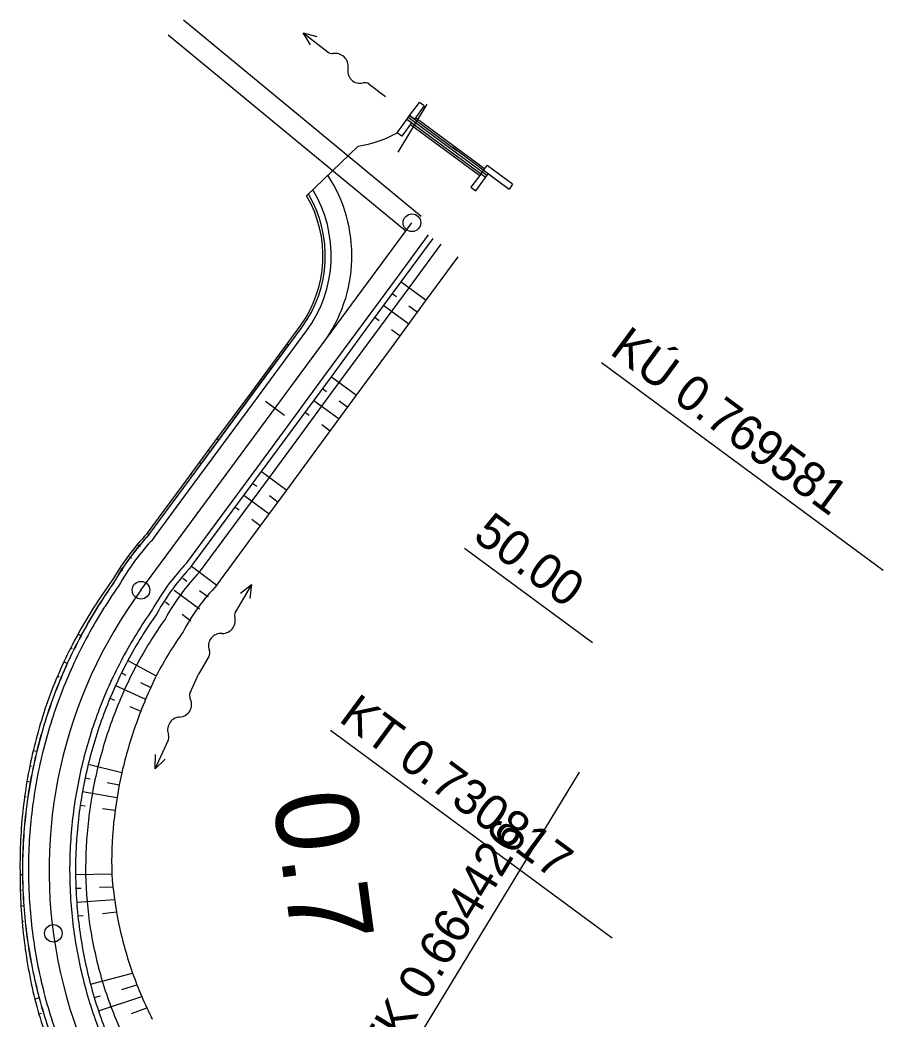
# Model space of a CAD drawing. Extents: x -481645 to -478728, y -1113199 to -1110710.
# Drawn here: x -479819.6 to -479746.4, y -1112732.9 to -1112648.1 of the extents above; entities that cross this region are included whole.
import ezdxf

# ---------------------------------------------------------------- set-up
doc = ezdxf.new("R2010")
doc.units = 0
for name, color, linetype in [('CP14_HECTOMETRY', 7, 'Continuous'), ('CP14_HLBODY', 7, 'Continuous'), ('CP14_HRANA_TELESO', 7, 'Continuous'), ('CP14_OSA', 7, 'Continuous'), ('CP14_PRIKOP', 7, 'Continuous'), ('CP14_STANICENI', 7, 'Continuous'), ('CP14_VOZOVKA', 7, 'Continuous'), ('CP14_ZPEVKRAJ', 7, 'Continuous'), ('CP1_HATCH_SLOPE_L', 7, 'Continuous'), ('CP1_HATCH_SLOPE_R', 7, 'Continuous'), ('CP1_HLBODY', 7, 'Continuous'), ('CP1_HRANA_TELESO', 7, 'Continuous'), ('CP1_OSA', 7, 'Continuous'), ('CP1_STANICENI', 7, 'Continuous'), ('CP1_VOZOVKA', 7, 'Continuous'), ('CP1_ZPEVKRAJ', 7, 'Continuous')]:
    doc.layers.add(name, color=color, linetype=linetype)

# ---------------------------------------------------------------- blocks, each defined once
blk = doc.blocks.new('A$C70B')
at = {"layer": 'CP14_HLBODY'}
for p, q in [((0.869, 0.002), (-0.869, -0.002)), ((6.861, 0.426), (7.971, -0.002)), ((7.971, -0.002), (5.275, -0.002)), ((7.971, -0.002), (6.862, -0.478))]:
    blk.add_line(p, q, dxfattribs=at)
for centre, radius, start, end in [((0.872, 0.584), 0.582, 269.69241, 322.79009), ((2.168, -0.416), 1.055, 24.40393, 142.08362), ((4.08, 0.589), 1.109, 210.88731, 317.37071), ((5.319, -0.636), 0.636, 85.97658, 131.72478)]:
    blk.add_arc(centre, radius, start, end, dxfattribs=at)

msp = doc.modelspace()

# ---------------------------------------------------------------- linework, layer by layer
at = {"layer": 'CP14_HRANA_TELESO'}
for p, q in [((-479796.825, -1112675.729), (-479796.948, -1112675.638)), ((-479797.632, -1112676.686), (-479797.69, -1112676.644)), ((-479797.567, -1112676.735), (-479797.571, -1112676.732)), ((-479798.309, -1112677.741), (-479798.432, -1112677.65)), ((-479799.116, -1112678.698), (-479799.174, -1112678.656)), ((-479799.05, -1112678.747), (-479799.054, -1112678.744)), ((-479802.76, -1112683.778), (-479802.915, -1112683.663)), ((-479803.584, -1112684.724), (-479803.657, -1112684.669)), ((-479803.502, -1112684.784), (-479803.506, -1112684.781)), ((-479804.244, -1112685.79), (-479804.399, -1112685.675)), ((-479805.068, -1112686.736), (-479805.141, -1112686.681)), ((-479804.986, -1112686.796), (-479804.99, -1112686.793)), ((-479808.695, -1112691.826), (-479808.846, -1112691.715)), ((-479809.52, -1112692.771), (-479809.594, -1112692.716)), ((-479809.437, -1112692.832), (-479809.441, -1112692.829)), ((-479810.179, -1112693.838), (-479810.342, -1112693.717)), ((-479811.01, -1112694.778), (-479811.09, -1112694.719)), ((-479810.921, -1112694.844), (-479810.925, -1112694.841)), ((-479814.453, -1112700.385), (-479814.714, -1112700.245)), ((-479815.199, -1112701.488), (-479815.333, -1112701.422)), ((-479815.056, -1112701.559), (-479815.06, -1112701.557)), ((-479815.622, -1112702.752), (-479815.914, -1112702.619)), ((-479816.308, -1112703.896), (-479816.457, -1112703.833)), ((-479816.15, -1112703.962), (-479816.155, -1112703.96)), ((-479818.213, -1112710.226), (-479818.526, -1112710.149)), ((-479818.663, -1112711.48), (-479818.809, -1112711.449)), ((-479818.507, -1112711.513), (-479818.512, -1112711.512)), ((-479818.76, -1112712.808), (-479819.052, -1112712.756)), ((-479819.118, -1112714.09), (-479819.253, -1112714.07)), ((-479818.973, -1112714.111), (-479818.978, -1112714.11)), ((-479819.422, -1112720.691), (-479819.633, -1112720.693)), ((-479819.508, -1112722.016), (-479819.617, -1112722.02)), ((-479819.388, -1112722.011), (-479819.393, -1112722.011)), ((-479819.313, -1112723.329), (-479819.56, -1112723.347)), ((-479819.334, -1112724.658), (-479819.461, -1112724.672)), ((-479819.197, -1112724.644), (-479819.202, -1112724.644)), ((-479818.004, -1112731.13), (-479818.386, -1112731.232)), ((-479817.843, -1112732.46), (-479818.032, -1112732.517)), ((-479817.645, -1112732.401), (-479817.649, -1112732.402))]:
    msp.add_line(p, q, dxfattribs=at)
at = {"layer": 'CP14_OSA'}
msp.add_circle((-479816.81, -1112725.652), 0.75, dxfattribs=at)
at = {"layer": 'CP14_PRIKOP'}
for p, q in [((-479787.268, -1112670.352), (-479785.157, -1112671.909)), ((-479788.01, -1112671.358), (-479787.673, -1112671.606)), ((-479788.752, -1112672.364), (-479786.633, -1112673.926)), ((-479786.616, -1112672.386), (-479785.895, -1112672.918)), ((-479789.494, -1112673.37), (-479789.156, -1112673.618)), ((-479788.095, -1112674.401), (-479787.371, -1112674.935)), ((-479793.203, -1112678.4), (-479791.07, -1112679.973)), ((-479793.945, -1112679.406), (-479793.608, -1112679.654)), ((-479794.687, -1112680.412), (-479792.55, -1112681.988)), ((-479792.54, -1112680.442), (-479791.81, -1112680.981)), ((-479795.429, -1112681.418), (-479795.092, -1112681.666)), ((-479794.023, -1112682.455), (-479793.291, -1112682.995)), ((-479799.138, -1112686.448), (-479796.992, -1112688.031)), ((-479799.88, -1112687.454), (-479799.543, -1112687.703)), ((-479800.622, -1112688.46), (-479798.473, -1112690.045)), ((-479798.469, -1112688.495), (-479797.732, -1112689.038)), ((-479801.364, -1112689.466), (-479801.027, -1112689.715)), ((-479799.951, -1112690.508), (-479799.213, -1112691.052)), ((-479805.074, -1112694.497), (-479802.914, -1112696.089)), ((-479805.815, -1112695.503), (-479805.478, -1112695.752)), ((-479806.557, -1112696.509), (-479804.387, -1112698.109)), ((-479804.396, -1112696.55), (-479803.651, -1112697.099)), ((-479807.299, -1112697.515), (-479806.962, -1112697.764)), ((-479805.875, -1112698.566), (-479805.124, -1112699.119)), ((-479810.482, -1112702.502), (-479808.07, -1112703.789)), ((-479811.021, -1112703.552), (-479810.646, -1112703.736)), ((-479811.527, -1112704.617), (-479808.978, -1112705.779)), ((-479809.406, -1112704.349), (-479808.54, -1112704.777)), ((-479811.999, -1112705.698), (-479811.61, -1112705.861)), ((-479810.303, -1112706.408), (-479809.384, -1112706.792)), ((-479813.842, -1112711.295), (-479810.986, -1112711.994)), ((-479814.105, -1112712.445), (-479813.69, -1112712.533)), ((-479812.243, -1112712.84), (-479811.211, -1112713.058)), ((-479814.331, -1112713.603), (-479811.404, -1112714.128)), ((-479814.521, -1112714.767), (-479814.101, -1112714.829)), ((-479812.622, -1112715.047), (-479811.563, -1112715.203)), ((-479814.922, -1112720.646), (-479811.846, -1112720.615)), ((-479814.892, -1112721.825), (-479814.458, -1112721.807)), ((-479812.885, -1112721.742), (-479811.747, -1112721.695)), ((-479814.825, -1112723.003), (-479811.614, -1112722.77)), ((-479814.721, -1112724.178), (-479814.274, -1112724.132)), ((-479812.637, -1112723.961), (-479811.447, -1112723.837)), ((-479813.655, -1112729.973), (-479810.083, -1112729.023)), ((-479811.007, -1112730.41), (-479809.71, -1112730.022)), ((-479813.334, -1112731.108), (-479812.819, -1112730.954)), ((-479812.978, -1112732.233), (-479809.306, -1112731.006)), ((-479810.185, -1112732.458), (-479808.873, -1112731.974))]:
    msp.add_line(p, q, dxfattribs=at)
at = {"layer": 'CP14_STANICENI'}
msp.add_line((-479795.305, -1112663.043), (-479790.933, -1112658.823), dxfattribs=at)
for centre, radius, start, end in [((-479792.206, -1112649.726), 9.185, 277.97005, 299.91517), ((-479803.963, -1112668.139), 10.75, 323.59269, 31.37909), ((-479803.993, -1112668.156), 10.081, 323.86732, 30.47383), ((-479803.963, -1112668.139), 10.25, 323.59269, 30.75296)]:
    msp.add_arc(centre, radius, start, end, dxfattribs=at)
at = {"layer": 'CP14_VOZOVKA'}
for p, q in [((-479805.765, -1112648.12), (-479785.577, -1112664.776)), ((-479807.065, -1112649.375), (-479786.877, -1112666.031)), ((-479787.52, -1112659.35), (-479785.056, -1112655.265))]:
    msp.add_line(p, q, dxfattribs=at)
msp.add_arc((-479803.963, -1112668.139), 12.5, 323.59269, 33.16788, dxfattribs=at)
at = {"layer": 'CP14_ZPEVKRAJ'}
for p, q in [((-479786.557, -1112656.24), (-479785.725, -1112655.113)), ((-479785.323, -1112655.41), (-479786.154, -1112656.537)), ((-479785.323, -1112655.41), (-479785.725, -1112655.113)), ((-479787.626, -1112657.688), (-479786.794, -1112656.561)), ((-479786.794, -1112656.561), (-479786.557, -1112656.24)), ((-479782.348, -1112659.845), (-479786.794, -1112656.561)), ((-479786.392, -1112656.858), (-479786.794, -1112656.561)), ((-479779.995, -1112661.333), (-479786.675, -1112656.4)), ((-479786.557, -1112656.239), (-479782.512, -1112659.226)), ((-479786.154, -1112656.537), (-479786.557, -1112656.24)), ((-479780.19, -1112660.754), (-479786.065, -1112656.416)), ((-479786.392, -1112656.858), (-479787.224, -1112657.985)), ((-479786.481, -1112656.979), (-479780.606, -1112661.318)), ((-479787.224, -1112657.985), (-479787.626, -1112657.688)), ((-479779.877, -1112661.172), (-479782.914, -1112658.929)), ((-479780.114, -1112661.494), (-479783.152, -1112659.251)), ((-479780.279, -1112660.875), (-479779.983, -1112660.472)), ((-479777.811, -1112662.067), (-479779.983, -1112660.472)), ((-479780.517, -1112661.197), (-479781.348, -1112662.323)), ((-479780.946, -1112662.62), (-479780.114, -1112661.494)), ((-479780.517, -1112661.197), (-479780.279, -1112660.875)), ((-479780.279, -1112660.875), (-479778.11, -1112662.468)), ((-479780.114, -1112661.494), (-479779.877, -1112661.172)), ((-479781.348, -1112662.323), (-479780.946, -1112662.62)), ((-479777.814, -1112662.065), (-479778.11, -1112662.468))]:
    msp.add_line(p, q, dxfattribs=at)
at = {"layer": 'CP1_HATCH_SLOPE_L'}
for p, q in [((-479797.177, -1112681.682), (-479798.786, -1112680.495)), ((-479781.885, -1112692.959), (-479771.02, -1112700.972))]:
    msp.add_line(p, q, dxfattribs=at)
at = {"layer": 'CP1_HATCH_SLOPE_R'}
for p, q in [((-479770.264, -1112677.2), (-479746.361, -1112694.828)), ((-479793.271, -1112708.398), (-479769.367, -1112726.025)), ((-479787.567, -1112737.356), (-479772.133, -1112711.981))]:
    msp.add_line(p, q, dxfattribs=at)
for centre in [(-479786.36, -1112665.33), (-479809.367, -1112696.527)]:
    msp.add_circle(centre, 0.75, dxfattribs=at)
at = {"layer": 'CP1_HLBODY'}
for p, q in [((-479787.67, -1112670.055), (-479784.952, -1112666.369)), ((-479790.638, -1112674.079), (-479787.67, -1112670.055)), ((-479793.605, -1112678.103), (-479790.638, -1112674.079)), ((-479796.573, -1112682.127), (-479793.605, -1112678.103)), ((-479802.358, -1112684.074), (-479799.39, -1112680.05)), ((-479799.541, -1112686.152), (-479796.573, -1112682.127)), ((-479805.325, -1112688.098), (-479802.358, -1112684.074)), ((-479802.508, -1112690.176), (-479799.541, -1112686.152)), ((-479808.293, -1112692.122), (-479805.325, -1112688.098)), ((-479805.476, -1112694.2), (-479802.508, -1112690.176))]:
    msp.add_line(p, q, dxfattribs=at)
for centre, radius, start, end in [((-479793.084, -1112706.422), 20.875, 136.76418, 150.61946), ((-479791.666, -1112707.43), 19.125, 136.22776, 151.14187), ((-479777.174, -1112720.268), 41.75, 144.76332, 151.92529), ((-479777.174, -1112720.268), 38.25, 144.76331, 151.92528), ((-479777.174, -1112720.268), 41.75, 151.92529, 159.08726), ((-479777.174, -1112720.268), 38.25, 151.92528, 159.08726), ((-479777.174, -1112720.268), 41.75, 159.08726, 166.24924), ((-479777.174, -1112720.268), 38.25, 159.08726, 166.24923), ((-479777.174, -1112720.268), 41.75, 166.24924, 173.41121), ((-479777.174, -1112720.268), 38.25, 166.24923, 173.4112), ((-479777.174, -1112720.268), 41.75, 173.41121, 180.57318), ((-479777.174, -1112720.268), 38.25, 173.4112, 180.57317), ((-479777.174, -1112720.268), 41.75, 180.57318, 187.73515), ((-479777.174, -1112720.268), 38.25, 180.57317, 187.73514), ((-479777.174, -1112720.268), 41.75, 187.73515, 194.89713), ((-479777.174, -1112720.268), 38.25, 187.73514, 194.89712), ((-479777.174, -1112720.268), 38.25, 194.89712, 202.05909), ((-479777.174, -1112720.268), 41.75, 194.89713, 202.0591)]:
    msp.add_arc(centre, radius, start, end, dxfattribs=at)
at = {"layer": 'CP1_HRANA_TELESO'}
for p, q in [((-479785.157, -1112671.909), (-479782.424, -1112668.234)), ((-479788.109, -1112675.944), (-479785.157, -1112671.909)), ((-479799.917, -1112679.662), (-479795.852, -1112674.1)), ((-479791.07, -1112679.973), (-479788.109, -1112675.944)), ((-479802.915, -1112683.663), (-479799.917, -1112679.662)), ((-479794.031, -1112684.002), (-479791.07, -1112679.973)), ((-479805.884, -1112687.687), (-479802.915, -1112683.663)), ((-479796.992, -1112688.031), (-479794.031, -1112684.002)), ((-479808.846, -1112691.715), (-479805.884, -1112687.687)), ((-479799.954, -1112692.06), (-479796.992, -1112688.031)), ((-479802.914, -1112696.089), (-479799.954, -1112692.06))]:
    msp.add_line(p, q, dxfattribs=at)
for centre, radius, start, end in [((-479793.441, -1112706.33), 21.234, 136.50563, 150.16536), ((-479777.505, -1112720.797), 42.508, 143.92415, 151.08689), ((-479790.322, -1112708.271), 17.52, 135.94864, 152.02132), ((-479777.336, -1112720.619), 42.571, 151.40625, 158.56852), ((-479777.072, -1112720.101), 35.029, 145.08335, 152.24543), ((-479776.743, -1112719.283), 34.949, 153.68312, 160.84848), ((-479777.12, -1112720.092), 42.583, 159.33516, 166.4972), ((-479777.005, -1112719.71), 34.845, 160.04478, 167.20775), ((-479777.104, -1112719.864), 42.546, 166.80102, 173.96332), ((-479777.085, -1112719.747), 34.776, 167.11831, 174.28111), ((-479777.152, -1112719.79), 42.49, 174.05545, 181.21788), ((-479777.15, -1112719.715), 34.708, 174.32379, 181.48668), ((-479777.136, -1112720.855), 42.497, 179.78211, 186.94476), ((-479777.416, -1112717.988), 34.53, 184.36389, 191.54165), ((-479777.797, -1112717.681), 34.22, 192.17183, 199.35546), ((-479777.009, -1112721.141), 42.589, 186.5414, 193.70493), ((-479778.169, -1112717.655), 33.879, 199.60558, 206.79196), ((-479777.083, -1112720.543), 42.663, 194.50961, 201.67174)]:
    msp.add_arc(centre, radius, start, end, dxfattribs=at)
at = {"layer": 'CP1_OSA'}
msp.add_line((-479809.367, -1112696.527), (-479786.36, -1112665.33), dxfattribs=at)
msp.add_arc((-479777.174, -1112720.268), 40, 143.59269, 238.69063, dxfattribs=at)
at = {"layer": 'CP1_STANICENI'}
for p, q in [((-479787.67, -1112670.055), (-479784.952, -1112666.369)), ((-479790.638, -1112674.079), (-479787.67, -1112670.055)), ((-479793.605, -1112678.103), (-479790.638, -1112674.079)), ((-479799.39, -1112680.05), (-479795.311, -1112674.52)), ((-479796.573, -1112682.127), (-479793.605, -1112678.103)), ((-479802.358, -1112684.074), (-479799.39, -1112680.05)), ((-479799.541, -1112686.152), (-479796.573, -1112682.127)), ((-479805.325, -1112688.098), (-479802.358, -1112684.074)), ((-479802.508, -1112690.176), (-479799.541, -1112686.152)), ((-479808.293, -1112692.122), (-479805.325, -1112688.098)), ((-479805.476, -1112694.2), (-479802.508, -1112690.176))]:
    msp.add_line(p, q, dxfattribs=at)
for centre, radius, start, end in [((-479793.084, -1112706.422), 20.875, 136.76418, 150.61946), ((-479791.666, -1112707.43), 19.125, 136.22776, 151.14187), ((-479777.174, -1112720.268), 41.75, 144.76332, 151.92529), ((-479777.174, -1112720.268), 38.25, 144.76331, 151.92528), ((-479777.174, -1112720.268), 41.75, 151.92529, 159.08726), ((-479777.174, -1112720.268), 38.25, 151.92528, 159.08726), ((-479777.174, -1112720.268), 41.75, 159.08726, 166.24924), ((-479777.174, -1112720.268), 38.25, 159.08726, 166.24923), ((-479777.174, -1112720.268), 41.75, 166.24924, 173.41121), ((-479777.174, -1112720.268), 38.25, 166.24923, 173.4112), ((-479777.174, -1112720.268), 41.75, 173.41121, 180.57318), ((-479777.174, -1112720.268), 38.25, 173.4112, 180.57317), ((-479777.174, -1112720.268), 41.75, 180.57318, 187.73515), ((-479777.174, -1112720.268), 38.25, 180.57317, 187.73514), ((-479777.174, -1112720.268), 41.75, 187.73515, 194.89713), ((-479777.174, -1112720.268), 38.25, 187.73514, 194.89712), ((-479777.174, -1112720.268), 38.25, 194.89712, 202.05909), ((-479777.174, -1112720.268), 41.75, 194.89713, 202.0591)]:
    msp.add_arc(centre, radius, start, end, dxfattribs=at)
at = {"layer": 'CP1_VOZOVKA'}
for p, q in [((-479787.268, -1112670.352), (-479784.55, -1112666.666)), ((-479790.235, -1112674.376), (-479787.268, -1112670.352)), ((-479799.792, -1112679.753), (-479795.714, -1112674.223)), ((-479793.203, -1112678.4), (-479790.235, -1112674.376)), ((-479796.171, -1112682.424), (-479793.203, -1112678.4)), ((-479802.76, -1112683.778), (-479799.792, -1112679.753)), ((-479799.138, -1112686.448), (-479796.171, -1112682.424)), ((-479805.728, -1112687.802), (-479802.76, -1112683.778)), ((-479802.106, -1112690.472), (-479799.138, -1112686.448)), ((-479808.695, -1112691.826), (-479805.728, -1112687.802)), ((-479805.073, -1112694.497), (-479802.106, -1112690.472))]:
    msp.add_line(p, q, dxfattribs=at)
for centre, radius, start, end in [((-479793.287, -1112706.278), 21.125, 136.83359, 150.55201), ((-479791.463, -1112707.574), 18.875, 136.14304, 151.22455), ((-479777.174, -1112720.268), 42.25, 144.76332, 151.92529), ((-479777.174, -1112720.268), 37.75, 144.76331, 151.92528), ((-479777.174, -1112720.268), 42.25, 151.92529, 159.08726), ((-479777.174, -1112720.268), 37.75, 151.92528, 159.08726), ((-479777.174, -1112720.268), 42.25, 159.08726, 166.24924), ((-479777.174, -1112720.268), 37.75, 159.08726, 166.24923), ((-479777.174, -1112720.268), 42.25, 166.24924, 173.41121), ((-479777.174, -1112720.268), 37.75, 166.24923, 173.4112), ((-479777.174, -1112720.268), 42.25, 173.41121, 180.57318), ((-479777.174, -1112720.268), 37.75, 173.4112, 180.57317), ((-479777.174, -1112720.268), 42.25, 180.57318, 187.73515), ((-479777.174, -1112720.268), 37.75, 180.57317, 187.73514), ((-479777.174, -1112720.268), 42.25, 187.73515, 194.89713), ((-479777.174, -1112720.268), 37.75, 187.73514, 194.89712), ((-479777.174, -1112720.268), 37.75, 194.89712, 202.05909), ((-479777.174, -1112720.268), 42.25, 194.89713, 202.0591)]:
    msp.add_arc(centre, radius, start, end, dxfattribs=at)
at = {"layer": 'CP1_ZPEVKRAJ'}
for p, q in [((-479786.594, -1112670.849), (-479783.875, -1112667.163)), ((-479789.561, -1112674.873), (-479786.594, -1112670.849)), ((-479792.529, -1112678.897), (-479789.561, -1112674.873)), ((-479799.8, -1112679.747), (-479796.833, -1112675.723)), ((-479795.497, -1112682.921), (-479792.529, -1112678.897)), ((-479802.768, -1112683.772), (-479799.8, -1112679.747)), ((-479798.464, -1112686.946), (-479795.497, -1112682.921)), ((-479805.736, -1112687.796), (-479802.768, -1112683.772)), ((-479801.432, -1112690.97), (-479798.464, -1112686.946)), ((-479808.703, -1112691.82), (-479805.736, -1112687.796)), ((-479804.399, -1112694.994), (-479801.432, -1112690.97))]:
    msp.add_line(p, q, dxfattribs=at)
for centre, radius, start, end in [((-479793.291, -1112706.275), 21.13, 136.83496, 150.55068), ((-479791.124, -1112707.815), 18.456, 135.99598, 151.36819), ((-479777.174, -1112720.268), 42.26, 144.76332, 151.92529), ((-479777.201, -1112720.312), 36.916, 144.68354, 151.84552), ((-479777.174, -1112720.268), 42.26, 151.92529, 159.08726), ((-479777.123, -1112720.156), 36.911, 152.11568, 159.27769), ((-479777.174, -1112720.268), 42.26, 159.08726, 166.24924), ((-479777.171, -1112720.259), 36.903, 159.10287, 166.26484), ((-479777.174, -1112720.268), 42.26, 166.24924, 173.41121), ((-479777.172, -1112720.259), 36.902, 166.26461, 173.42658), ((-479777.174, -1112720.268), 42.26, 173.41121, 180.57318), ((-479777.172, -1112720.218), 36.898, 173.48881, 180.65079), ((-479777.174, -1112720.268), 42.26, 180.57318, 187.73515), ((-479777.21, -1112719.81), 36.866, 181.28645, 188.44898), ((-479777.375, -1112719.329), 36.777, 189.2276, 196.39201), ((-479777.174, -1112720.268), 42.26, 187.73515, 194.89713), ((-479777.633, -1112718.977), 36.632, 197.03356, 204.20053), ((-479777.174, -1112720.268), 42.26, 194.89713, 202.0591)]:
    msp.add_arc(centre, radius, start, end, dxfattribs=at)

# ---------------------------------------------------------------- block references
at = {"layer": 'CP14_HECTOMETRY'}
for p, rotation in [((-479789.305, -1112654.098), 142.2083198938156), ((-479804.038, -1112702.9), 59.384220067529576), ((-479804.839, -1112704.44), -114.58073141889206)]:
    msp.add_blockref('A$C70B', p, dxfattribs=dict(at, rotation=rotation))

# ---------------------------------------------------------------- texts
at = {"layer": 'CP14_OSA'}
msp.add_text('0.7', height=7, rotation=277.68952, dxfattribs=at).set_placement((-479798.202, -1112714))
at = {"layer": 'CP1_HATCH_SLOPE_L'}
msp.add_text('50.00', height=2.999, rotation=323.5927, dxfattribs=at).set_placement((-479781.292, -1112692.154))
at = {"layer": 'CP1_HATCH_SLOPE_R'}
for s, height, rotation, p in [('KÚ 0.769581', 2.999, 323.5927, (-479769.671, -1112676.395)), ('KT 0.730817', 2.999, 323.5927, (-479792.678, -1112707.593)), ('TK 0.664426', 3, 58.69064, (-479788.422, -1112736.837))]:
    msp.add_text(s, height=height, rotation=rotation, dxfattribs=at).set_placement(p)

doc.saveas('drawing.dxf')
